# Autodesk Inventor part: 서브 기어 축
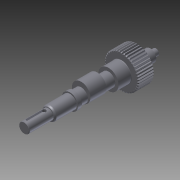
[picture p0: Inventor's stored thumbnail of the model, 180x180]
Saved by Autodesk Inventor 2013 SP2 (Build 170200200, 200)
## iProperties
Created: 2018-12
Part Number: 서브 기어 축
Material: 강철, 연강
Document SubType Name: Modeling
Designer: mduedu
Categories: <?xml version="1.0" encoding="UTF-16"?> <MemberInstance><Categories><FamilyTemplate><FamilyTemplateParameter ValueType="xs:double" Id="1" ObjectReferenceKey="da
Density: 1 g/cm^3
Author: mduedu
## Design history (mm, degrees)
sketch "Sketch1"
  geometry: C1 r 21.3 at (0, 0)
  constraints: 1 centre point
  dimensions: "d0" = 42.6 diameter of C1 (= da_da)
extrude "Extrusion1" new body sketch "Sketch1" distance "d1" = 20 (= da_b); taper "d2" = 0 deg
workplane "Work Plane2"
sketch "Sketch2"
  geometry: C1 r 21.3 at (0, 0) reference; C2 r 20.5 at (0, 0)
  constraints: 1 centre point, 1 coincident
  dimensions: "d3" = 41 diameter of C2 (= da_dw)
feature "피치 지름" sketch "Sketch2" dims "d4" = 10, "d5" = 0
workplane "Work Plane8"
workplane "Work Plane9"
chamfer "모따기1" distance "d49" = 1; stored, may be unused: second distance "d50" = 2, angle "d51" = 45 deg
sketch "스케치3"
  geometry: C1 r 12.5 at (0, 0); 1 further point
  constraints: 1 centre point, 1 coincident
  dimensions: "d52" = 25 diameter of C1
extrude "돌출2" join sketch "스케치3" distance "d53" = 16; taper "d54" = 0 deg
sketch "스케치4"
  geometry: C1 r 8.5 at (0, 0); 1 further point
  constraints: 1 centre point, 1 coincident
  dimensions: "d55" = 17 diameter of C1
extrude "돌출3" join sketch "스케치4" distance "d56" = 105; taper "d57" = 0 deg
sketch "스케치5"
  geometry: C1 r 7.5 at (0, 0); 1 further point
  constraints: 1 centre point, 1 coincident
  dimensions: "d58" = 15 diameter of C1
extrude "돌출4" join sketch "스케치5" distance "d59" = 16; taper "d60" = 0 deg
sketch "스케치6"
  geometry: C1 r 4 at (0, 0); 1 further point
  constraints: 1 centre point, 1 coincident
  dimensions: "d61" = 8 diameter of C1
extrude "돌출5" join sketch "스케치6" distance "d62" = 7; taper "d63" = 0 deg
fillet "모깎기1" dims "d67" = 0.5
feature "스퍼 기어" dims "da_b" = 20, "da_d" = 41, "da_aw" = 31, "da_da" = 42.6, "da_df" = 39.086, "da_dw" = 41, angle "da_beta" = 0 deg, "da_lefttooth" = 0, "da_righttooth" = 0
node "작업 평면11"
sketch "스케치7"
  geometry: C1 r 11.5 at (0, 3); C2 r 8.5 at (0, 0) reference; 1 further point
  constraints: 1 centre point, 1 tangent, 1 vertical alignment
  dimensions: "d69" = 3 distance of point (0, 0) C1.centre; "d70" = 23 diameter of C1 (derived)
extrude "돌출6" join sketch "스케치7" stored distance "d71" = 20; taper "d72" = 0 deg
node "작업 평면12"
sketch "스케치8"
  geometry: C1 r 12.5 at (0, 0) reference; C2 r 10 at (0, 0); 1 further point
  constraints: 1 centre point, 1 coincident
  dimensions: "d110" = 20 diameter of C2
extrude "돌출7" join sketch "스케치8" distance "d74" = 5; taper "d75" = 0 deg
sketch "스케치14"
  geometry: L1 (-11.5, 111)-(-6.5, 111); L2 (-6.5, 111)-(-6.5, 141); L3 (-6.5, 141)-(-11.5, 141); L4 (-11.5, 141)-(-11.5, 111); L5 (8.5, 141)-(-8.5, 141) reference; L6 (0, 0)-(0, 141)
  constraints: 10 end point, 2 parallel, 1 collinear, 1 horizontal, 1 midpoint, 1 perpendicular
  dimensions: "d92" = 30 distance between parallel lines of L1 L5; "d93" = 13 diameter of L2 L6; "d95" = 5 distance of L2.end L3.end
revolve "회전2" sketch "스케치14" stored, may be unused: angle "d96" = 90 deg
chamfer "모따기4" distance "d97" = 0.5; stored, may be unused: second distance "d98" = 2, angle "d99" = 45 deg
revolve "회전1" stored, may be unused: angle "d82" = 90 deg
sketch "스케치10"
  geometry: L1 (-6.5, 117.5)-(-5, 116) reference; L2 (-6.5, 114.5)-(-5, 116) reference; 2 further points
  constraints: 1 coincident
node "작업점1"
node "작업 평면13"
sketch "스케치11"
  geometry: L1 (-2.5, 9.5)-(-2.5, -9.5); L2 (2.5, -9.5)-(2.5, 9.5); L3 (-6, 15)-(6, 15) reference; A1 r 2.5 centre (0, 9.5) between (2.5, 9.5) and (-2.5, 9.5); A2 r 2.5 centre (0, -9.5) between (-2.5, -9.5) and (2.5, -9.5); 1 further point
  constraints: 4 end point, 4 point on circle, 4 tangent, 2 centre point, 2 vertical alignment, 1 parallel
  dimensions: "d84" = 24 dimension on A2 A1; "d85" = 5 distance between parallel lines of L1 L2; "d108" = 3 distance edge to line of A1 L3
extrude "돌출8" cut sketch "스케치11" distance "d86" = 3; taper "d87" = 0 deg
sketch "스케치12" dims "d88" = 32
  geometry: C1 r 0.5 at (0, -16); 2 further points
  constraints: 2 vertical alignment, 1 centre point, 1 coincident, 2 other
  dimensions: "d89" = 1 diameter of C1
extrude "돌출9" join sketch "스케치12" distance "d90" = 0.3; taper "d91" = 0 deg
sketch "스케치13"
  geometry: C1 r 11.5 at (0, 3) reference; 1 further point
  node "절단 모서리 투영1"
sketch "스케치15"
  geometry: L1 (-8.5, 109.181)-(-7.45, 111); L2 (-8.5, 111)-(8.5, 111) reference; L3 (-8.5, 84)-(-8.5, 111) reference; L4 (0, 0)-(0, 111); L5 (-7.45, 111)-(-8.5, 111); L6 (-8.5, 109.181)-(-8.5, 111)
  constraints: 8 end point, 2 collinear, 2 point on line, 1 midpoint
  dimensions: "d103" = 14.9 diameter of L1.end L4; "d104" = 30 deg angle of L3 L1
revolve "회전3" sketch "스케치15" stored, may be unused: angle "d105" = 90 deg
fillet "모깎기2" dims "d106" = 2
fillet "모깎기3" dims "d107" = 1
chamfer "모따기5" distance "d112" = 0.5; stored, may be unused: second distance "d113" = 2, angle "d114" = 45 deg
body "Solid1"
body "Srf1"
node "투영된 루프1"
sketch "스케치9"
  geometry: L1 (0, 138.97)-(0, 0); L2 (-6.5, 116)-(0, 116); L3 (-6.5, 116)-(-6.5, 114.5); L4 (-6.5, 114.5)-(-5, 116); L5 (-5, 116)-(-6.5, 116); L6 (-6, 141)-(6, 141) reference
  constraints: 10 end point, 2 point on line, 1 collinear, 1 vertical
  dimensions: "d80" = 3 diameter of L3.end L2; "d100" = 25 distance between parallel lines of L6 L2; "d101" = 6.5 distance between parallel lines of L1 L3; "d102" = 45 deg angle of L4 L3
other parameters: "d16" = 31 (= da_aw), "d17" = 0, "d34" = 0.76624 (computed from da_z), "d39" = 0, "d41" = 0, "d43" = 31 (= da_aw), "d46" = 31 (= da_aw), "d47" = 0, "d48" = 0
